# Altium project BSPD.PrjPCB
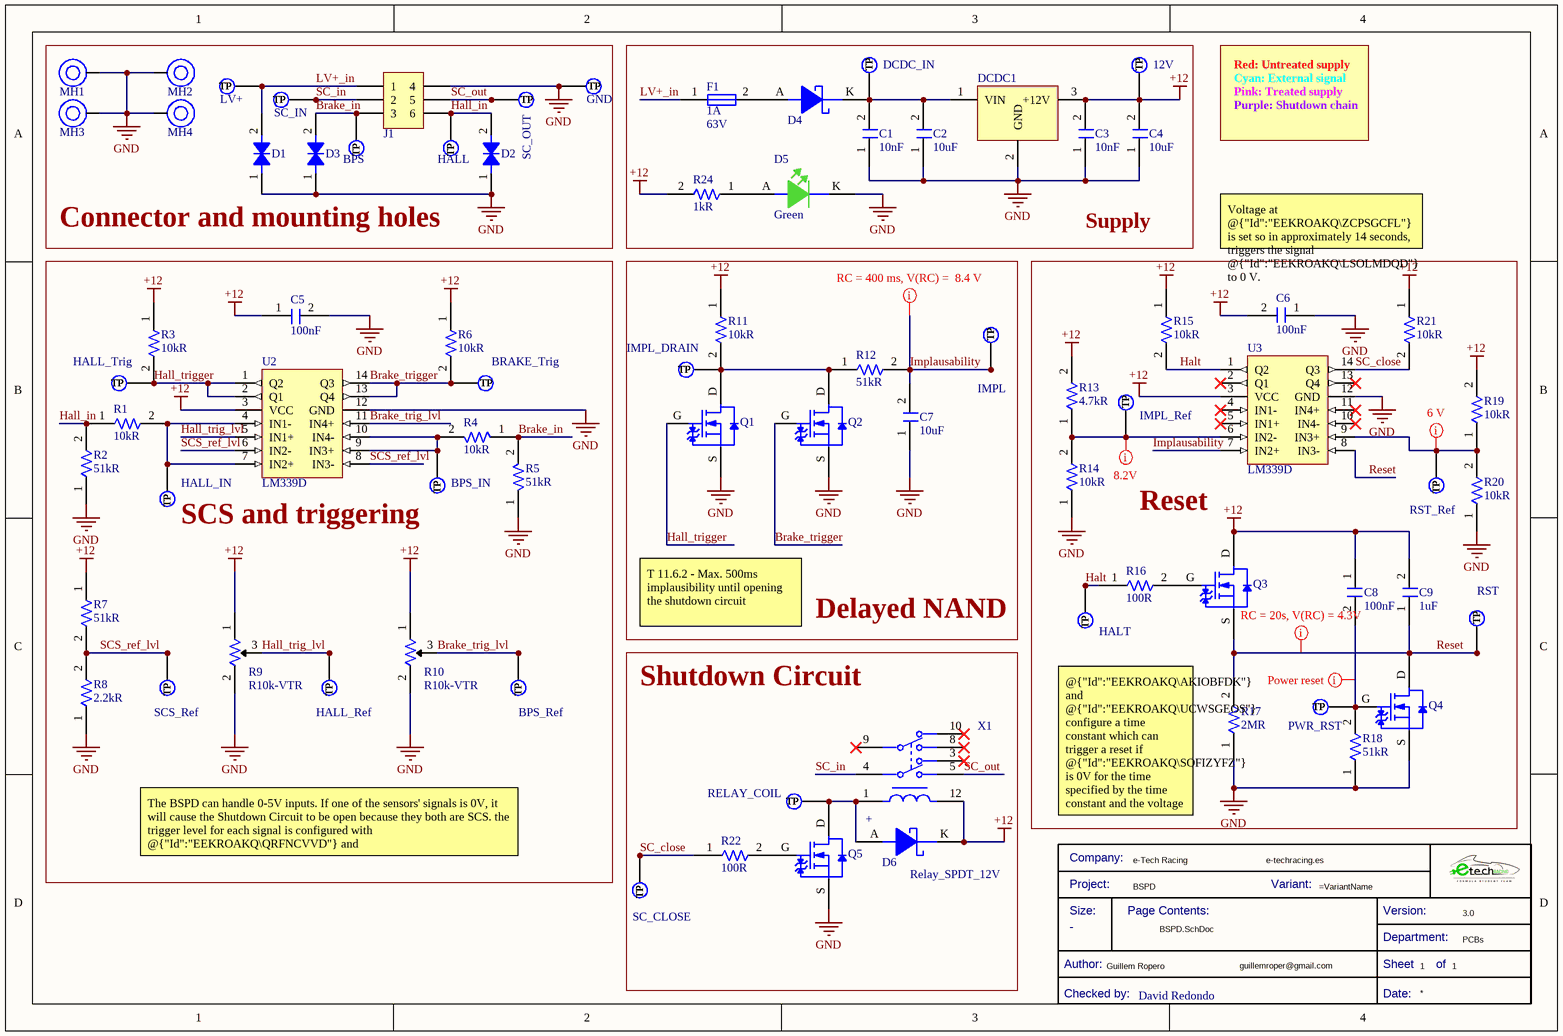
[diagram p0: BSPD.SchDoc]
Company: e-Tech Racing; Department: PCBs; DesignedByURL: e-techracing.es; DesignerMail: guillemroper@gmail.com; DesignerName: Guillem Ropero; Project: BSPD; ReviewerName: David Redondo; Version: 3.0
1 sheet, 78 parts. Net scope: global (net labels, ports and power ports of the same name join across sheets).
Board files: BSPD.PcbDoc, BSPD_2025.PcbDoc

## Sheet BSPD.SchDoc
size A4; SheetNumber: 1; SheetTotal: 1

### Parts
12V  TestPoint  [TestPoint]  (value not drawn)  (no BOM)
*  Checked by:: David Redondo  (hidden comment: Title Block_template)  (graphical)
BPS  TestPoint  [TestPoint]  (value not drawn)  (no BOM)
BPS_IN  TestPoint  [TestPoint]  (value not drawn)  (no BOM)
BPS_Ref  TestPoint  [TestPoint]  (value not drawn)  (no BOM)
BRAKE_Trig  TestPoint  [TestPoint]  (value not drawn)  (no BOM)
C1  Capacitance: 10nF  [C1206FNPC-RW]  (hidden comment: 885012008055)
C2  Capacitance: 10uF  [C10u-50V-1210FNPMLCC-X7R]  (hidden comment: GRJ32ER71H106KE11L)
C3  Capacitance: 10nF  [C1206FNPC-RW]  (hidden comment: 885012008055)
C4  Capacitance: 10uF  [C10u-50V-1210FNPMLCC-X7R]  (hidden comment: GRJ32ER71H106KE11L)
C5  Capacitance: 100nF  [C1206FNPC-RW]  (hidden comment: 885012208058)
C6  Capacitance: 100nF  [C1206FNPC-RW]  (hidden comment: 885012208058)
C7  Capacitance: 10uF  [C1206FNPC-RW]  (hidden comment: 885012208018)
C8  Capacitance: 100nF  [C1206FNPC-RW]  (hidden comment: 885012208058)
C9  Capacitance: 1uF  [C1206FNPC-RW]  (hidden comment: 885012208036)
D1  824551301  [DTVS-DO-214AB]  (value not drawn)
D2  824501600  [DTVS-DO-214AC]  (value not drawn)
D3  824501600  [DTVS-DO-214AC]  (value not drawn)
D4  MBR0530  [DSC-SOD123]  (value not drawn)
D5  Color: Green  [LED_0805_WE]  (hidden comment: 150080VS75000)
D6  MBR0530  [DSC-SOD123]  (value not drawn)
DCDC1  173951236  [DCDC_Magi3c]  (value not drawn)
DCDC_IN  TestPoint  [TestPoint]  (value not drawn)  (no BOM)
F1  Current Rating: 1A  Voltage Rating (DC): 63V  [Fuse_1206]  (hidden comment: 0437001.WRA)
GND  TestPoint  [TestPoint]  (value not drawn)  (no BOM)
HALL  TestPoint  [TestPoint]  (value not drawn)  (no BOM)
HALL_IN  TestPoint  [TestPoint]  (value not drawn)  (no BOM)
HALL_Ref  TestPoint  [TestPoint]  (value not drawn)  (no BOM)
HALL_Trig  TestPoint  [TestPoint]  (value not drawn)  (no BOM)
HALT  TestPoint  [TestPoint]  (value not drawn)  (no BOM)
IMPL  TestPoint  [TestPoint]  (value not drawn)  (no BOM)
IMPL_DRAIN  TestPoint  [TestPoint]  (value not drawn)  (no BOM)
IMPL_Ref  TestPoint  [TestPoint]  (value not drawn)  (no BOM)
J1  J_NanoFit_2x3  [J_NanoFit_2x3]  (value not drawn)
LV+  TestPoint  [TestPoint]  (value not drawn)  (no BOM)
MH1  Mounting_Hole_M3  [Mounting_Hole_M3]  (value not drawn)
MH2  Mounting_Hole_M3  [Mounting_Hole_M3]  (value not drawn)
MH3  Mounting_Hole_M3  [Mounting_Hole_M3]  (value not drawn)
MH4  Mounting_Hole_M3  [Mounting_Hole_M3]  (value not drawn)
PWR_RST  TestPoint  [TestPoint]  (value not drawn)  (no BOM)
Q1  CPH3455-TL-H  [TRT-NCH-3/35-CPH]  (value not drawn)
Q2  CPH3455-TL-H  [TRT-NCH-3/35-CPH]  (value not drawn)
Q3  CPH3455-TL-H  [TRT-NCH-3/35-CPH]  (value not drawn)
Q4  CPH3455-TL-H  [TRT-NCH-3/35-CPH]  (value not drawn)
Q5  CPH3455-TL-H  [TRT-NCH-3/35-CPH]  (value not drawn)
R1  Resistance: 10kR  [R1206FTK-W]  (hidden comment: CRCW120610K0FKEA)
R2  Resistance: 51kR  [R1206FTK-W]  (hidden comment: CRCW120610K0FKEA)
R3  Resistance: 10kR  [R1206FTK-W]  (hidden comment: CRCW120610K0FKEA)
R4  Resistance: 10kR  [R1206FTK-W]  (hidden comment: CRCW120610K0FKEA)
R5  Resistance: 51kR  [R1206FTK-W]  (hidden comment: CRCW120610K0FKEA)
R6  Resistance: 10kR  [R1206FTK-W]  (hidden comment: CRCW120610K0FKEA)
R7  Resistance: 51kR  [R1206FTK-W]  (hidden comment: CRCW120610K0FKEA)
R8  Resistance: 2.2kR  [R1206FTK-W]  (hidden comment: CR1206-FX-2201ELF)
R9  R10k-VTR  [R10k-VTR]
R10  R10k-VTR  [R10k-VTR]
R11  Resistance: 10kR  [R1206FTK-W]  (hidden comment: CRCW120610K0FKEA)
R12  Resistance: 51kR  [R1206FTK-W]  (hidden comment: CRCW120610K0FKEA)
R13  Resistance: 4.7kR  [R1206FTK-W]  (hidden comment: CRS1206-FX-4701ELF)
R14  Resistance: 10kR  [R1206FTK-W]  (hidden comment: CRCW120610K0FKEA)
R15  Resistance: 10kR  [R1206FTK-W]  (hidden comment: CRCW120610K0FKEA)
R16  Resistance: 100R  [R1206FTK-W]  (hidden comment: CRG1206F100R)
R17  Resistence: 2MR  [R1206FTK-W]  (hidden comment: HVC1206-2M0FT3)
R18  Resistance: 51kR  [R1206FTK-W]  (hidden comment: CRCW120610K0FKEA)
R19  Resistance: 10kR  [R1206FTK-W]  (hidden comment: CRCW120610K0FKEA)
R20  Resistance: 10kR  [R1206FTK-W]  (hidden comment: CRCW120610K0FKEA)
R21  Resistance: 10kR  [R1206FTK-W]  (hidden comment: CRCW120610K0FKEA)
R22  Resistance: 100R  [R1206FTK-W]  (hidden comment: CRG1206F100R)
R24  Resistance: 1kR  [R0805FTK]  (hidden comment: CR0805-JW-102ELF)
RELAY_COIL  TestPoint  [TestPoint]  (value not drawn)  (no BOM)
RST  TestPoint  [TestPoint]  (value not drawn)  (no BOM)
RST_Ref  TestPoint  [TestPoint]  (value not drawn)  (no BOM)
SC_CLOSE  TestPoint  [TestPoint]  (value not drawn)  (no BOM)
SC_IN  TestPoint  [TestPoint]  (value not drawn)  (no BOM)
SC_OUT  TestPoint  [TestPoint]  (value not drawn)  (no BOM)
SCS_Ref  TestPoint  [TestPoint]  (value not drawn)  (no BOM)
U2  LM339D  [Array_4_Amp_LM339D]
U3  LM339D  [Array_4_Amp_LM339D]
X1  Relay_SPDT_12V  [FP-4-1393789-5-0]

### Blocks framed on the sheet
Connector and mounting holes: BPS D1-D3 GND HALL J1 LV+ MH1-MH4 SC_IN SC_OUT
Supply: 12V C1-C4 D4 D5 DCDC1 DCDC_IN F1 R24
SCS and triggering: BPS_IN BPS_Ref BRAKE_Trig C5 HALL_IN HALL_Ref HALL_Trig R1-R10 SCS_Ref U2
Delayed NAND: C7 IMPL IMPL_DRAIN Q1 Q2 R11 R12
Reset: C6 C8 C9 HALT IMPL_Ref PWR_RST Q3 Q4 R13-R21 RST RST_Ref U3
Shutdown Circuit: D6 Q5 R22 RELAY_COIL SC_CLOSE X1

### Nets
+12: 12V.1(TP) C3.2 C4.2 C5.1 C6.2 C8.1 C9.2 D6.K DCDC1.3(+12V) Q3.D R3.1 R6.1 R7.1 R9.1 R10.1 R11.1 R13.2 R15.1 R19.2 R21.1 R24.2 U2.3(VCC) U3.3(VCC) X1.12
GND: C1.1 C2.1 C3.1 C4.1 C5.2 C6.1 C7.1 D1.1 D2.1 D3.1 D5.K DCDC1.2(GND) GND.1(TP) J1.4 MH1.1 MH2.1 MH3.1 MH4.1 Q1.S Q2.S Q4.S Q5.S R2.1 R5.1 R8.1 R9.2 R10.2 R14.1 R17.1 R18.1 R20.1 U2.12(GND) U3.12(GND)
Brake_in: BPS.1(TP) D3.2 J1.3 R4.1 R5.2
Brake_trig_lvl: BPS_Ref.1(TP) R10.3 U2.11(IN4+)
Brake_trigger: BRAKE_Trig.1(TP) Q2.G R6.2 U2.13(Q4) U2.14(Q3)
Hall_in: D2.2 HALL.1(TP) J1.6 R1.1 R2.2
Hall_trig_lvl: HALL_Ref.1(TP) R9.3 U2.5(IN1+)
Hall_trigger: HALL_Trig.1(TP) Q1.G R3.2 U2.1(Q2) U2.2(Q1)
Halt: HALT.1(TP) R15.2 R16.1 U3.1(Q2)
Implausability: C7.2 IMPL.1(TP) R12.2 U3.7(IN2+)
LV+_in: D1.2 F1.1 J1.1 LV+.1(TP)
Reset: C9.1 Q3.S Q4.D R17.2 RST.1(TP) U3.8(IN3-)
SC_close: R21.2 R22.1 SC_CLOSE.1(TP) U3.14(Q3)
SC_in: J1.2 SC_IN.1(TP) X1.4
SC_out: J1.5 SC_OUT.1(TP) X1.5
SCS_ref_lvl: R7.2 R8.2 SCS_Ref.1(TP) U2.6(IN2-) U2.8(IN3-)
NetBPS_IN_1: BPS_IN.1(TP) R4.2 U2.9(IN3+) U2.10(IN4-)
NetC1_2: C1.2 C2.2 D4.K DCDC1.1(VIN) DCDC_IN.1(TP)
NetC8_2: C8.2 PWR_RST.1(TP) Q4.G R18.2
NetD4_A: D4.A F1.2
NetD5_A: D5.A R24.1
NetD6_A: D6.A Q5.D RELAY_COIL.1(TP) X1.1
NetHALL_IN_1: HALL_IN.1(TP) R1.2 U2.4(IN1-) U2.7(IN2+)
NetIMPL_DRAIN_1: IMPL_DRAIN.1(TP) Q1.D Q2.D R11.2 R12.1
NetIMPL_Ref_1: IMPL_Ref.1(TP) R13.1 R14.2 U3.6(IN2-)
NetQ3_G: Q3.G R16.2
NetQ5_G: Q5.G R22.2
NetR19_1: R19.1 R20.2 RST_Ref.1(TP) U3.9(IN3+)

Not connected (* = marked no-connect by the designer): U3 2(Q1)* 4(IN1-)* 5(IN1+)* 10(IN4-)* 11(IN4+)* 13(Q4)*; X1 3* 8* 9* 10*

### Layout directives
mark named RC = 400 ms, V(RC) =  8.4 V: Implausability
mark named 8.2V: NetIMPL_Ref_1
mark named 6 V: NetR19_1
mark named RC = 20s, V(RC) = 4.3V: Reset
mark named Power reset: NetC8_2

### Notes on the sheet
- Cyan: External signal
- Red: Untreated supply
- Purple: Shutdown chain
- Pink: Treated supply
- Voltage at @{"Id":"EEKROAKQ\ZCPSGCFL"} is set so in approximately 14 seconds, triggers the signal @{"Id":"EEKROAKQ\LSOLMDQD"} to 0 V.
- T 11.6.2 - Max. 500ms implausibility until opening the shutdown circuit
- The BSPD can handle 0-5V inputs. If one of the sensors' signals is 0V, it will cause the Shutdown Circuit to be open because they both are SCS. the trigger level for each signal is configured with @{"Id":"EEKROAKQ\QRFNCVVD"} and @{"Id":"EEKROAKQ\DXJUVPGI"} .
- @{"Id":"EEKROAKQ\AKIOBFDK"} and @{"Id":"EEKROAKQ\UCWSGEOS"} configure a time constant which can trigger a reset if @{"Id":"EEKROAKQ\SOFIZYFZ"} is 0V for the time specified by the time constant and the voltage reference achieved with @{"Id":"EEKROAKQ\OZTMMTKS"} and @{"Id":"EEKROAKQ\ALONRRDI"}. This is due to T 11.6.1

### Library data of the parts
12V BPS BPS_IN BPS_Ref BRAKE_Trig DCDC_IN GND HALL HALL_IN HALL_Ref HALL_Trig HALT IMPL IMPL_DRAIN IMPL_Ref LV+ PWR_RST RELAY_COIL RST RST_Ref SC_CLOSE SC_IN SC_OUT SCS_Ref = TestPoint: Test Point 1x1 mm; .Creator: GP
* = Title Block_template: Standard Title Block; .Creator: GP
C1 C3 = C10n-50V-1206FNPC-C0G/NP0: Cap Cer 10000PF 50V C0G/NP0 1206; Manufacturer: Wurth Electronics; Tolerance: 5%; .Creator: DO
C2 C4 = C10u-50V-1210FNPMLCC-X7R: Multilayer Ceramic Capacitors MLCC - SMD/SMT 1210 10uF 50volts X7R +/-10% Soft Term; Manufacturer: Murata; Voltage Rating: 50V; Tolerance: 10%; .Creator: DR
C5 C6 C8 = C100n-25V-1206FNPC-X7R: Cap Cer 0.1UF 25V X7R 1206; Manufacturer: Wurth Electronics; Tolerance: 10%; .Creator: DO
C7 = C10u-10V-1206FNPC-X7R: Cap, 10ΜF, 10V, 10%, X7R, 1206; Manufacturer 1: Wurth Electronics; .Creator: GP
C9 = C1u-16V-1206FNPC-X7R: Cap Cer 1UF 16V X7R 1206; Manufacturer: Wurth Electronics; Tolerance: 10%; .Creator: GP
D1 = DTVS-40V-DO-214AB: TVS diode [Würth Elektronik] 824551301 TVS diode; Manufacturer: Wurth Electronics; Number of Bidirectional Channels: 1; Reverse Standoff Voltage: 30V; Min Breakdown Voltage: 35.05V; Clamping Voltage: 48.4V; Peak Pulse Power: 3kW; Power Line Protection: No; Polarity: Bidirectional; Peak Pulse Current: 62A; .Creator: DO
D2 D3 = DTVS-6V-DO-214AC: TVS diode [Würth Elektronik] 824501600 TVS diode; Manufacturer: Wurth Electronics; Number of Bidirectional Channels: 1; Reverse Standoff Voltage: 6V; Min Breakdown Voltage: 7.02V; Clamping Voltage: 10.3V; Peak Pulse Power: 400W; Power Line Protection: No; Polarity: Bidirectional; Peak Pulse Current: 38.8A; .Creator: DO
D4 D6 = DSC-0.5/30-SOD123: VR=30V IF=500mA 30pF P=410mW; Element Configuration: Single; Forward Voltage: 430mV; Peak Non-Repetitive Surge Current: 5.5A; Average Rectified Current: 500mA; Max Reverse Leakage Current: 130uA; Max Reverse Voltage (DC): 30V; Polarity: Standard; .Creator: GP
D5 = LEDVS-0805-40: Led, Green, 570 Nm, 2 V, 30 Ma, 40 Mcd Rohs Compliant: Yes; Manufacturer 1: Wurth Electronics; Luminous Intensity: 40mcd; Forward Current: 30mA; Forward Voltage: 2V; Viewing Angle: 140°; Wavelength: 570nm; Lens Style: Clear,Rectangular; Test Current: 20mA; .Creator: DR
DCDC1 = DCDC-36V/12V-0.5A: Fdsm Fixed Step Down Regulator M; Manufacturer 1: Wurth Electronics
F1 = Fuse_1A_63V_1206: Fuse Chip Fast Acting 1A 63V SMD Solder Pad 1206 Ceramic T/R Automotive; Manufacturer: Littelfuse; Fuse Type: Board Mount (Cartridge Style Excluded); Approvals: CSA,cURus; .Creator: DO
Q1-Q5 = TRT-NCH-3/35-CPH: CPH3455-TL-H N-channel MOSFET Transistor; 3 A; 35 V; 3-Pin CPH; Manufacturer: ON Semiconductor; Rds On Max: 104mR; Input Capacitance: 186pF; Rise Time: 4.7ns; Drain to Source Voltage (Vdss): 35V; Continuous Drain Current (ID): 3A; Max Power Dissipation: 1W; Drain to Source Resistance: 108mR; Turn-On Delay Time: 4.2ns; Turn-Off Delay Time: 15ns; Fall Time: 5.7ns; Element Configuration: Single; Gate to Source Voltage (Vgs): 20V; .Creator: GP
R1 R3 R4 R6 R11 R14 R15 R19-R21 = R10k-1206FTK: Res Thick Film 1206 10K Ohm 1% 0.25W(1/4W) +/-100ppm/ßC Pad SMD Automotive T/R; Temperature Coefficient: 100ppm/°C; Voltage Rating: 200V; .Creator: GP
R2 R5 R7 R12 R18 = R51k-1206FTK: Res Thick Film 1206 51K Ohm 1% 1/4W ±100ppm/°C Molded SMD SMD Punched Carrier T/R; Manufacturer: Panasonic; Manufacturer Part Number: ERJ-S08F5102V; Power Rating: 250mW; Voltage Rating: 150V; Voltage Rating (DC): 200V; Current Rating: 2A; .Creator: DO
R8 = R2.2K-1206FTK: Res Thick Film 1206 2.2K Ohm 1% 1/4W ±100ppm/°C Molded SMD SMD Paper Tape on Plastic Reel; Manufacturer 1: Bourns; Power Rating: 250mW; Voltage Rating: 200V; .Creator: AC
R9 R10 = CMP-00072-1: Trimmer, Cermet, Rest 10 Kilohms, PCB, 25 Turns, Pwr-Rtg 0.5W, 3296 Series; Manufacturer Part Number: 3296W-1-103LF; Manufacturer: Bourns; Insulation Resistance: 1GR; Max Power Dissipation: 500mW; .Creator: DO; Tolerance: 10%; Value: 10k; Number of Turns: 25; Temperature Coefficient: 100ppm/°C
R13 = R4.7K-1206FTK: Res Thick Film 1206 4.7K Ohm 1% 1/2W ±100ppm/°C Molded SMD T/R; Manufacturer 1: Bourns JW Miller; Voltage Rating: 400V; Power Rating: 500mW; .Creator: AC
R16 R22 = R100-1206FTK: Res Thick Film 1206 100 Ohm 1% 0.25W(1/4W) ±200ppm/C Pad SMD T/R; Manufacturer: TE Connectivity; Temperature Coefficient: 200ppm/°C; Max Power Dissipation: 250mW; Voltage Rating: 200V; Number of Resistors: 1; .Creator: AC
R17 = R2M-1206FTK: Res Thick Film 1206 2M Ohm 1% 0.3W ±100ppm/C Pad SMD T/R; Manufacturer: TT Welwyn; Power Rating: 300mW; Voltage Rating: 1kV; Temperature Coefficient: 100ppm/°C; .Creator: DO
R24 = R1k-0805FTK: Res Thick Film 0805 1K Ohm 5% 1/8W ±200ppm/°C Molded SMD SMD Paper Tape on Plastic Reel; Manufacturer 1: Bourns; Voltage Rating (DC): 150V; Power Rating: 125mW; .Creator: GP
U2 U3 = Array_4_Comp_LM339D: Comparator Quad ±18V/36V 14-Pin SOIC Tube; Manufacturer: Texas Instruments; Number of Channels: 4; Nominal Supply Current: 2mA; Output Current: 20mA; Quiescent Current: 2.5mA; Max Supply Voltage: 30V; Min Supply Voltage: 2V; Min Dual Supply Voltage: 1V; Max Dual Supply Voltage: 15V; Voltage Gain: 106.02dB; Max Supply Current: 500uA; Input Bias Current: 250nA; Output Current per Channel: 6mA; Input Offset Voltage (Vos): 5mV; Response Time: 0.3us; Output Type: TTL; Dual Supply Voltage: 9V; .Creator: DO
X1 = CMP-00219-1: RF Relay, 2 Form C, DPDT, Momentary, 0.012A (Coil), 12VDC (Coil), 140mW (Coil), 5A (Contact), 220VDC (Contact), 900MHz, 60W (RF Input), DC Input, Random, AC/DC Output, Surface Mount-Straight; Manufacturer Series: 1393789; Dielectric Strength Between Open Contacts: 1000Vrms; Contact DC Max Rating R Load: 5A@220VDC; Contact AC Max Rating R Load: 5A@250VAC; Relay Form: 2 FORM C; Release Time: 9ms; Isolation-Max: -39dB; Insulation Resistance: 1GR; Body Height: 9.9mm; Sealing: IP67/RT3; Coil Operate Voltage(DC): 26.15V; Coil Release Voltage(DC): 1.2V; Coil Resistance: 1.029kR; End Contact Plating: Gold; Dielectric Strength Between Coil and Contacts: 1500Vrms; End Contact Material: Silver; Switching Time: 16ms; Contact AC Max Power Rating R Load: 62.5VA@250VAC; Insertion Loss-Max: -0.02dB; Reference Standard: UL; PCB Hole Count: 10; Coil Voltage-Nom: 12V; Contact DC Max Power Rating R Load: 60W@220VDC; VSWR: 1.4; Coil Current(DC)-Max: 12mA; Operating Frequency-Min: 100MHz; Body Breadth: 7.2mm; Contact Voltage(AC)-Max: 250V; Operate Time: 7ms; Contact Voltage(DC)-Max: 220V; Body Length or Diameter: 14.6mm; Contact Resistance: 50mR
